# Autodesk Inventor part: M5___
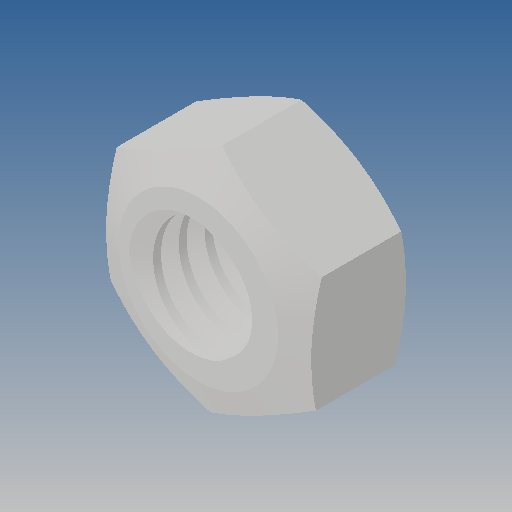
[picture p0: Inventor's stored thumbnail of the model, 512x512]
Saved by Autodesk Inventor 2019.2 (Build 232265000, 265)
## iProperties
Created: 2010-06
Part Number: M5___
Material: Ogólny
Document SubType Name: Modeling
Designer: CADENGINEERING4
Density: 1 g/cm^3
Appearance: Domyślna
Author: CADENGINEERING4
Revision Number: ANY
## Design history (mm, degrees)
feature "NONE"
node "Bryła1"
